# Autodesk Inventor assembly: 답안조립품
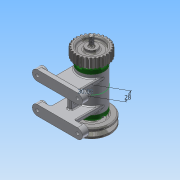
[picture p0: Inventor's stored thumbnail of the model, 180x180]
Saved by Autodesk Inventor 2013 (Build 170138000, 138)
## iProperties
Created: 2015-11
Part Number: 답안조립품
Document SubType Name: Assembly
Designer: user-11
Author: user-11
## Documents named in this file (10)
- C:\Users\user-11\Desktop\451109V1028\답안조립품.iam
- C:\Users\user-11\Desktop\451109V1028\1-본체.ipt
- C:\Users\user-11\Desktop\451109V1028\커버.ipt
- C:\Users\user-11\Desktop\451109V1028\베어링 15 x 32 x 9.ipt
- C:\Users\user-11\Desktop\451109V1028\축.ipt
- C:\Users\user-11\Desktop\451109V1028\키 3 x 3 x 12.ipt
- C:\Users\user-11\Desktop\451109V1028\오일 실 15 25 7.ipt
- C:\Users\user-11\Desktop\451109V1028\V벨트풀리.ipt
- C:\Users\user-11\Desktop\451109V1028\스퍼기어.ipt
- C:\Users\user-11\Desktop\451109V1028\볼트 M4 x 12.ipt
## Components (12 placed, 4 different names)
1. 1-본체:1
2. KS B 2023 6002 - 15 x 32 x 9:1
3. KS B 2023 6002 - 15 x 32 x 9:2
4. V벨트풀리:1 — 각도:3
5. ISO 4762 M4 x 12:5
6. ISO 4762 M4 x 12:6
7. ISO 4762 M4 x 12:7
8. ISO 4762 M4 x 12:8
9. ISO 4762 M4 x 12:1
10. ISO 4762 M4 x 12:2
11. ISO 4762 M4 x 12:3
12. ISO 4762 M4 x 12:4
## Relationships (1: Angle 1)
- 각도:3 [Angle]: V벨트풀리:1
